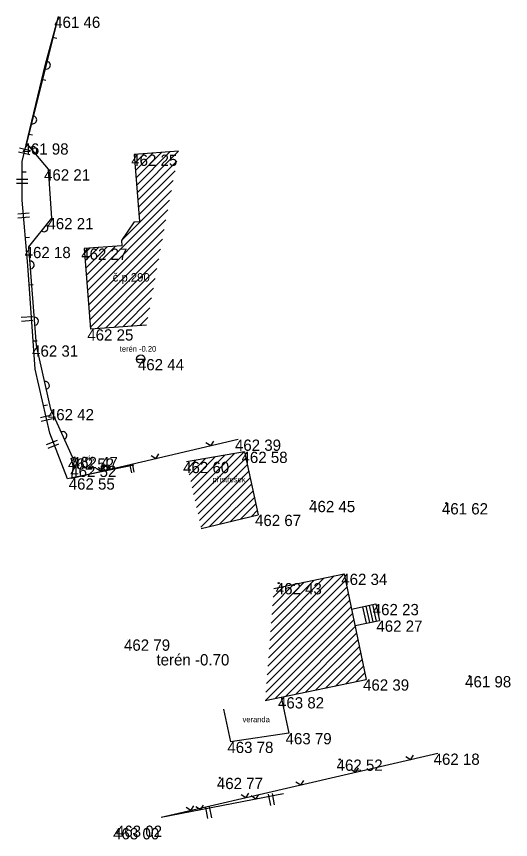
# Model space of a CAD drawing. Extents: x -553731 to -553573, y -1076100 to -1075378.
# Drawn here: x -553715.9 to -553672, y -1075450.7 to -1075377.7 of the extents above; entities that cross this region are included whole.
import ezdxf

# ---------------------------------------------------------------- set-up
doc = ezdxf.new("R2010")
doc.units = 0
for name, color, linetype in [('1', 7, 'Continuous'), ('12', 7, 'Continuous'), ('14', 7, 'Continuous'), ('18', 7, 'Continuous'), ('32', 7, 'Continuous'), ('52', 7, 'Continuous'), ('54', 7, 'Continuous'), ('6', 7, 'Continuous'), ('62', 7, 'Continuous')]:
    doc.layers.add(name, color=color, linetype=linetype)

# ---------------------------------------------------------------- blocks, each defined once
blk = doc.blocks.new('POINT_DISPLAY')
blk.add_line((0, 0), (0, 0))
blk = doc.blocks.new('ST')
at = {"layer": '1'}
blk.add_line((-0.375, 0), (0.375, 0), dxfattribs=at)
blk.add_circle((0, 0), 0.375, dxfattribs=at)
blk = doc.blocks.new('T')
at = {"layer": '6'}
blk.add_circle((0, 0), 0.05, dxfattribs=at)
blk = doc.blocks.new('ROV')
at = {"layer": '62'}
for p, q in [((-0.348, -0.51), (-0.348, 0.51)), ((0, -0.51), (0, 0.51))]:
    blk.add_line(p, q, dxfattribs=at)

msp = doc.modelspace()

# ---------------------------------------------------------------- linework, layer by layer
at = {"layer": '12'}
for p, q in [((-553714.97, -1075388.97), (-553712.17, -1075377.73)), ((-553713.07, -1075391.27), (-553714.97, -1075388.97)), ((-553712.77, -1075395.59), (-553713.07, -1075391.27)), ((-553714.79, -1075398.15), (-553712.77, -1075395.59)), ((-553714.13, -1075406.89), (-553714.79, -1075398.15)), ((-553712.85, -1075412.53), (-553714.13, -1075406.89)), ((-553710.893, -1075416.846), (-553712.85, -1075412.53)), ((-553696.22, -1075415.24), (-553710.99, -1075418.68)), ((-553698.655, -1075415.807), (-553698.39, -1075415.382)), ((-553698.655, -1075415.807), (-553699.08, -1075415.543)), ((-553703.525, -1075416.941), (-553703.95, -1075416.677)), ((-553703.525, -1075416.941), (-553703.26, -1075416.516)), ((-553710.99, -1075418.68), (-553710.85, -1075417.56)), ((-553708.394, -1075418.075), (-553708.819, -1075417.811)), ((-553708.394, -1075418.075), (-553708.13, -1075417.65)), ((-553678.49, -1075443.09), (-553703.07, -1075448.76)), ((-553680.926, -1075443.652), (-553681.351, -1075443.387)), ((-553680.926, -1075443.652), (-553680.661, -1075443.227)), ((-553685.798, -1075444.776), (-553686.223, -1075444.51)), ((-553685.798, -1075444.776), (-553685.533, -1075444.351)), ((-553690.67, -1075445.9), (-553691.095, -1075445.634)), ((-553690.67, -1075445.9), (-553690.405, -1075445.475)), ((-553695.542, -1075447.024), (-553695.967, -1075446.758)), ((-553695.542, -1075447.024), (-553695.277, -1075446.599)), ((-553700.414, -1075448.147), (-553700.839, -1075447.882)), ((-553700.414, -1075448.147), (-553700.149, -1075447.723))]:
    msp.add_line(p, q, dxfattribs=at)
for centre, start, end in [((-553713.242, -1075382.032), 256.01174, 76.01174), ((-553714.45, -1075386.884), 256.01174, 76.01174), ((-553714.439, -1075389.612), 309.55967, 129.55967), ((-553713.458, -1075396.462), 231.72435, 51.72435), ((-553714.668, -1075399.76), 274.31849, 94.31849), ((-553714.292, -1075404.746), 274.31849, 94.31849), ((-553713.326, -1075410.433), 282.7867, 102.7867), ((-553711.781, -1075414.888), 294.39092, 114.39092)]:
    msp.add_arc(centre, 0.35, start, end, dxfattribs=at)
at = {"layer": '14'}
for p, q in [((-553701.507, -1075389.673), (-553705.44, -1075389.97)), ((-553705.44, -1075389.97), (-553704.993, -1075395.893)), ((-553705.452, -1075395.928), (-553706.574, -1075397.579)), ((-553705.452, -1075395.928), (-553704.993, -1075395.893)), ((-553706.574, -1075397.579), (-553706.539, -1075398.048)), ((-553706.539, -1075398.048), (-553709.88, -1075398.3)), ((-553709.88, -1075398.3), (-553709.34, -1075405.46)), ((-553704.354, -1075405.084), (-553709.34, -1075405.46)), ((-553695.65, -1075416.32), (-553700.82, -1075417.22)), ((-553695.65, -1075416.32), (-553694.44, -1075421.91)), ((-553699.497, -1075423.118), (-553694.44, -1075421.91)), ((-553693.057, -1075428.447), (-553686.81, -1075427.14)), ((-553686.81, -1075427.14), (-553684.85, -1075436.51)), ((-553693.835, -1075438.382), (-553684.85, -1075436.51))]:
    msp.add_line(p, q, dxfattribs=at)
at = {"layer": '18'}
for p, q in [((-553711.05, -1075416.91), (-553710.73, -1075416.78)), ((-553710.53, -1075417.43), (-553710.73, -1075416.78)), ((-553710.85, -1075417.56), (-553711.05, -1075416.91)), ((-553710.85, -1075417.56), (-553710.53, -1075417.43)), ((-553686.155, -1075430.271), (-553684, -1075429.82)), ((-553684.88, -1075430.004), (-553684.561, -1075431.474)), ((-553684.587, -1075429.943), (-553684.267, -1075431.413)), ((-553684.293, -1075429.881), (-553683.973, -1075431.351)), ((-553684, -1075429.82), (-553683.68, -1075431.29)), ((-553685.174, -1075430.066), (-553684.854, -1075431.535)), ((-553685.847, -1075431.743), (-553683.68, -1075431.29)), ((-553692.41, -1075438.09), (-553691.73, -1075441.27)), ((-553697.512, -1075439.147), (-553696.91, -1075442.04)), ((-553691.73, -1075441.27), (-553696.91, -1075442.04))]:
    msp.add_line(p, q, dxfattribs=at)
at = {"layer": '32'}
for p, q in [((-553705.334, -1075391.378), (-553703.802, -1075389.846)), ((-553705.284, -1075392.036), (-553703.037, -1075389.789)), ((-553705.234, -1075392.693), (-553702.272, -1075389.731)), ((-553705.185, -1075393.351), (-553701.507, -1075389.673)), ((-553705.433, -1075390.063), (-553705.331, -1075389.962)), ((-553705.383, -1075390.721), (-553704.566, -1075389.904)), ((-553705.135, -1075394.008), (-553701.667, -1075390.54)), ((-553705.086, -1075394.666), (-553701.827, -1075391.408)), ((-553705.036, -1075395.323), (-553701.988, -1075392.275)), ((-553706.552, -1075397.546), (-553702.148, -1075393.142)), ((-553709.65, -1075401.351), (-553702.308, -1075394.01)), ((-553709.6, -1075402.009), (-553702.468, -1075394.877)), ((-553709.551, -1075402.666), (-553702.629, -1075395.744)), ((-553709.501, -1075403.324), (-553702.789, -1075396.612)), ((-553709.452, -1075403.981), (-553702.949, -1075397.479)), ((-553709.848, -1075398.721), (-553709.39, -1075398.263)), ((-553709.799, -1075399.379), (-553708.625, -1075398.205)), ((-553709.749, -1075400.036), (-553707.86, -1075398.148)), ((-553709.699, -1075400.694), (-553707.096, -1075398.09)), ((-553709.402, -1075404.639), (-553703.109, -1075398.346)), ((-553709.352, -1075405.297), (-553703.27, -1075399.214)), ((-553708.765, -1075405.417), (-553703.43, -1075400.081)), ((-553708.001, -1075405.359), (-553703.59, -1075400.948)), ((-553707.236, -1075405.301), (-553703.75, -1075401.816)), ((-553706.471, -1075405.244), (-553703.91, -1075402.683)), ((-553705.706, -1075405.186), (-553704.071, -1075403.55)), ((-553704.941, -1075405.128), (-553704.231, -1075404.418)), ((-553700.431, -1075418.953), (-553698.252, -1075416.773)), ((-553700.302, -1075419.53), (-553697.395, -1075416.624)), ((-553700.172, -1075420.108), (-553696.539, -1075416.475)), ((-553700.043, -1075420.685), (-553695.683, -1075416.326)), ((-553699.913, -1075421.263), (-553695.529, -1075416.879)), ((-553700.69, -1075417.798), (-553699.964, -1075417.071)), ((-553700.561, -1075418.375), (-553699.108, -1075416.922)), ((-553699.784, -1075421.84), (-553695.403, -1075417.46)), ((-553699.654, -1075422.418), (-553695.277, -1075418.041)), ((-553699.524, -1075422.996), (-553695.152, -1075418.623)), ((-553698.765, -1075422.943), (-553695.026, -1075419.204)), ((-553697.836, -1075422.721), (-553694.9, -1075419.785)), ((-553696.907, -1075422.499), (-553694.774, -1075420.366)), ((-553695.978, -1075422.277), (-553694.648, -1075420.948)), ((-553695.049, -1075422.055), (-553694.522, -1075421.529)), ((-553693.538, -1075434.584), (-553686.686, -1075427.733)), ((-553693.478, -1075433.817), (-553686.808, -1075427.148)), ((-553693.417, -1075433.05), (-553687.692, -1075427.325)), ((-553693.357, -1075432.283), (-553688.586, -1075427.512)), ((-553693.297, -1075431.516), (-553689.48, -1075427.699)), ((-553693.598, -1075435.352), (-553686.564, -1075428.318)), ((-553693.237, -1075430.749), (-553690.374, -1075427.886)), ((-553693.177, -1075429.981), (-553691.269, -1075428.073)), ((-553693.117, -1075429.214), (-553692.163, -1075428.26)), ((-553693.658, -1075436.119), (-553686.441, -1075428.902)), ((-553693.718, -1075436.886), (-553686.319, -1075429.487)), ((-553693.79, -1075438.373), (-553686.074, -1075430.657)), ((-553693.778, -1075437.653), (-553686.197, -1075430.072)), ((-553692.897, -1075438.187), (-553685.952, -1075431.242)), ((-553692.004, -1075438), (-553685.83, -1075431.826)), ((-553691.111, -1075437.814), (-553685.707, -1075432.411)), ((-553690.217, -1075437.628), (-553685.585, -1075432.996)), ((-553689.324, -1075437.442), (-553685.463, -1075433.581)), ((-553688.431, -1075437.256), (-553685.34, -1075434.165)), ((-553687.538, -1075437.07), (-553685.218, -1075434.75)), ((-553686.645, -1075436.884), (-553685.096, -1075435.335)), ((-553685.751, -1075436.698), (-553684.973, -1075435.92)), ((-553684.858, -1075436.512), (-553684.851, -1075436.505))]:
    msp.add_line(p, q, dxfattribs=at)
at = {"layer": '62'}
for p, q in [((-553713.31, -1075381.95), (-553712.17, -1075377.73)), ((-553712.658, -1075379.537), (-553712.32, -1075379.628)), ((-553715.4, -1075390.57), (-553713.31, -1075381.95)), ((-553713.633, -1075383.281), (-553713.293, -1075383.364)), ((-553714.811, -1075388.14), (-553714.471, -1075388.223)), ((-553715.38, -1075394), (-553715.4, -1075390.57)), ((-553715.395, -1075391.5), (-553715.045, -1075391.498)), ((-553714.9, -1075399.81), (-553715.38, -1075394)), ((-553715.106, -1075397.318), (-553714.757, -1075397.29)), ((-553714.23, -1075408.99), (-553714.9, -1075399.81)), ((-553714.776, -1075401.51), (-553714.427, -1075401.484)), ((-553714.412, -1075406.497), (-553714.063, -1075406.471)), ((-553712.94, -1075414.67), (-553714.23, -1075408.99)), ((-553713.494, -1075412.232), (-553713.152, -1075412.155)), ((-553711.36, -1075418.72), (-553712.94, -1075414.67)), ((-553705.483, -1075417.507), (-553711.36, -1075418.72)), ((-553707.931, -1075418.012), (-553707.656, -1075417.594)), ((-553707.931, -1075418.012), (-553708.35, -1075417.737)), ((-553692.205, -1075446.656), (-553703.07, -1075448.76)), ((-553694.659, -1075447.131), (-553694.379, -1075446.716)), ((-553694.659, -1075447.131), (-553695.074, -1075446.851)), ((-553699.568, -1075448.082), (-553699.983, -1075447.802)), ((-553699.568, -1075448.082), (-553699.288, -1075447.667))]:
    msp.add_line(p, q, dxfattribs=at)

# ---------------------------------------------------------------- block references
at = {"layer": '1'}
for name, p in [('POINT_DISPLAY', (-553712.17, -1075377.73)), ('POINT_DISPLAY', (-553714.97, -1075388.97)), ('POINT_DISPLAY', (-553705.44, -1075389.97)), ('POINT_DISPLAY', (-553713.07, -1075391.27)), ('POINT_DISPLAY', (-553712.77, -1075395.59)), ('POINT_DISPLAY', (-553714.79, -1075398.15)), ('POINT_DISPLAY', (-553709.88, -1075398.3)), ('POINT_DISPLAY', (-553709.34, -1075405.46)), ('POINT_DISPLAY', (-553714.13, -1075406.89)), ('ST', (-553704.87, -1075408.1)), ('POINT_DISPLAY', (-553704.87, -1075408.1)), ('POINT_DISPLAY', (-553712.85, -1075412.53)), ('POINT_DISPLAY', (-553696.22, -1075415.24)), ('POINT_DISPLAY', (-553710.73, -1075416.78)), ('POINT_DISPLAY', (-553695.65, -1075416.32)), ('POINT_DISPLAY', (-553711.05, -1075416.91)), ('POINT_DISPLAY', (-553710.85, -1075417.56)), ('POINT_DISPLAY', (-553700.82, -1075417.22)), ('POINT_DISPLAY', (-553710.99, -1075418.68)), ('POINT_DISPLAY', (-553689.66, -1075420.68)), ('POINT_DISPLAY', (-553677.74, -1075420.88)), ('POINT_DISPLAY', (-553694.44, -1075421.91)), ('POINT_DISPLAY', (-553686.81, -1075427.14)), ('POINT_DISPLAY', (-553692.62, -1075427.97)), ('POINT_DISPLAY', (-553684, -1075429.82)), ('POINT_DISPLAY', (-553683.68, -1075431.29)), ('POINT_DISPLAY', (-553706.07, -1075432.97)), ('POINT_DISPLAY', (-553703.22, -1075435.19)), ('POINT_DISPLAY', (-553684.85, -1075436.51)), ('POINT_DISPLAY', (-553675.68, -1075436.22)), ('POINT_DISPLAY', (-553692.41, -1075438.09)), ('POINT_DISPLAY', (-553691.73, -1075441.27)), ('POINT_DISPLAY', (-553696.91, -1075442.04)), ('POINT_DISPLAY', (-553678.49, -1075443.09)), ('POINT_DISPLAY', (-553687.21, -1075443.62)), ('POINT_DISPLAY', (-553697.84, -1075445.24)), ('POINT_DISPLAY', (-553707.04, -1075449.7)), ('POINT_DISPLAY', (-553706.79, -1075449.48))]:
    msp.add_blockref(name, p, dxfattribs=at)
at = {"layer": '32'}
for p in [(-553701.507, -1075389.673), (-553700.82, -1075417.22), (-553693.057, -1075428.447)]:
    msp.add_blockref('POINT_DISPLAY', p, dxfattribs=at)
at = {"layer": '6'}
for p in [(-553689.66, -1075420.68), (-553677.74, -1075420.88), (-553692.62, -1075427.97), (-553675.68, -1075436.22), (-553687.21, -1075443.62), (-553697.84, -1075445.24)]:
    msp.add_blockref('T', p, dxfattribs=at)
at = {"layer": '62'}
for p, xscale, yscale, rotation in [((-553715.22, -1075389.829), 0.9999996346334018, 0.9999996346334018, -103.62902206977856), ((-553715.389, -1075392.49), 0.99999836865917, 0.9999983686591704, -89.6659580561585), ((-553715.255, -1075395.519), 1.000000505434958, 1.000000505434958, -85.27728213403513), ((-553714.941, -1075404.702), 0.9999986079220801, 0.9999986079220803, -85.82561080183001), ((-553713.277, -1075413.188), 0.9999998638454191, 0.9999998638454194, 102.7955976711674), ((-553712.775, -1075415.518), 1.0000015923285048, 1.0000015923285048, 111.31185616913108), ((-553705.759, -1075417.865), 0.6400023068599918, 0.6400023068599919, -168.33785587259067), ((-553693.462, -1075447.192), 0.9999983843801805, 0.9999983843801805, -169.04043653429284), ((-553699.026, -1075448.362), 0.9999983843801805, 0.9999983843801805, -169.04043653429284)]:
    msp.add_blockref('ROV', p, dxfattribs=dict(at, xscale=xscale, yscale=yscale, rotation=rotation))

# ---------------------------------------------------------------- texts
at = {"layer": '52'}
for s, p in [('terén -0.20', (-553706.728, -1075407.442)), ('pris', (-553710.075, -1075417.147)), ('přístřešek', (-553698.498, -1075419.029)), ('veranda', (-553695.827, -1075440.313))]:
    msp.add_text(s, height=0.5, dxfattribs=at).set_placement(p)
at = {"layer": '54'}
msp.add_text('č.p.290', height=0.75, dxfattribs=at).set_placement((-553707.361, -1075401.226))
at = {"layer": '6'}
for s, p in [('461 46 ', (-553712.553, -1075378.73)), ('461 98 ', (-553715.365, -1075389.97)), ('462 25 ', (-553705.714, -1075390.97)), ('462 21 ', (-553713.451, -1075392.27)), ('462 21 ', (-553713.151, -1075396.59)), ('462 18 ', (-553715.173, -1075399.15)), ('462 27 ', (-553710.152, -1075399.3)), ('462 25 ', (-553709.614, -1075406.46)), ('462 31 ', (-553714.511, -1075407.89)), ('462 44 ', (-553705.12, -1075409.1)), ('462 42 ', (-553713.112, -1075413.53)), ('462 39 ', (-553696.506, -1075416.24)), ('462 47 ', (-553710.99, -1075417.78)), ('462 58 ', (-553695.924, -1075417.32)), ('462 52 ', (-553711.324, -1075417.91)), ('462 52 ', (-553711.124, -1075418.56)), ('462 60 ', (-553701.108, -1075418.22)), ('462 55 ', (-553711.264, -1075419.68)), ('462 45 ', (-553689.922, -1075421.68)), ('461 62 ', (-553678.135, -1075421.88)), ('462 67 ', (-553694.724, -1075422.91)), ('462 34 ', (-553687.072, -1075428.14)), ('462 43 ', (-553692.882, -1075428.97)), ('462 23 ', (-553684.274, -1075430.82)), ('462 27 ', (-553683.952, -1075432.29)), ('462 79 ', (-553706.354, -1075433.97)), ('terén -0.70', (-553703.473, -1075435.272)), ('462 39 ', (-553685.136, -1075437.51)), ('461 98 ', (-553676.075, -1075437.22)), ('463 82 ', (-553692.684, -1075439.09)), ('463 79 ', (-553692.014, -1075442.27)), ('463 78 ', (-553697.182, -1075443.04)), ('462 18 ', (-553678.873, -1075444.09)), ('462 52 ', (-553687.484, -1075444.62)), ('462 77 ', (-553698.11, -1075446.24)), ('463 00 ', (-553707.318, -1075450.7)), ('463 02 ', (-553707.066, -1075450.48))]:
    msp.add_text(s, height=1, dxfattribs=at).set_placement(p)

doc.saveas('drawing.dxf')
